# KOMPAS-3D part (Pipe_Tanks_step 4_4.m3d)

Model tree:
1. X Axis
2. Y Axis
3. Z Axis  (labels: Valve Dy 150; Pipe Dn 150; T-Bend Dn 150)
     Òîëùèíà ñòåíêè 1 = 1

Referenced files in C:\Documents and Settings\kashirsky\Мои документы\Camtasia Studio\Pipelines3D\Tanks\: Tanks_step 4.a3d
Referenced files in C:\Program Files\ASCON\KOMPAS-3D V10\Libs\Piping\LOAD\: Piping_C_Pipe_150_1000.m3d
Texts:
  Pipe Dn 150
  Steel ASTM A295
  Three Point Plane
  Plane at Angle
  Line and Point Plane
  Axis through Two Vertices
  Axis of Feature
  Axis of Conical Surface
  Axis through Edge
  Trim by Surface
  Trim by Sketch
  Feature with No History
  Intersection Axis of Two Planes
  Two Line Plane
  Line and Face Plane
  Bend by line
  Hole in sheet body
  Cut in sheet body
  Point in CM
  Linear Dimension from Line to Point
  Surface Finish Symbol
  Geometric Tolerance Symbol
  Leader #1
  Leader #2
  Leader #3
  Shape Deviations and Datum
  Node point number
  Mark of coordination axis
  Node point designation
  Mark/Reference designation with leader
  Mark/reference designation on line
  Mark/Reference designation without leader
  Valve Dy 150
  T-Bend Dn 150
  Plane of section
